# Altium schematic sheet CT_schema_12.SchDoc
size 390 x 278 mm
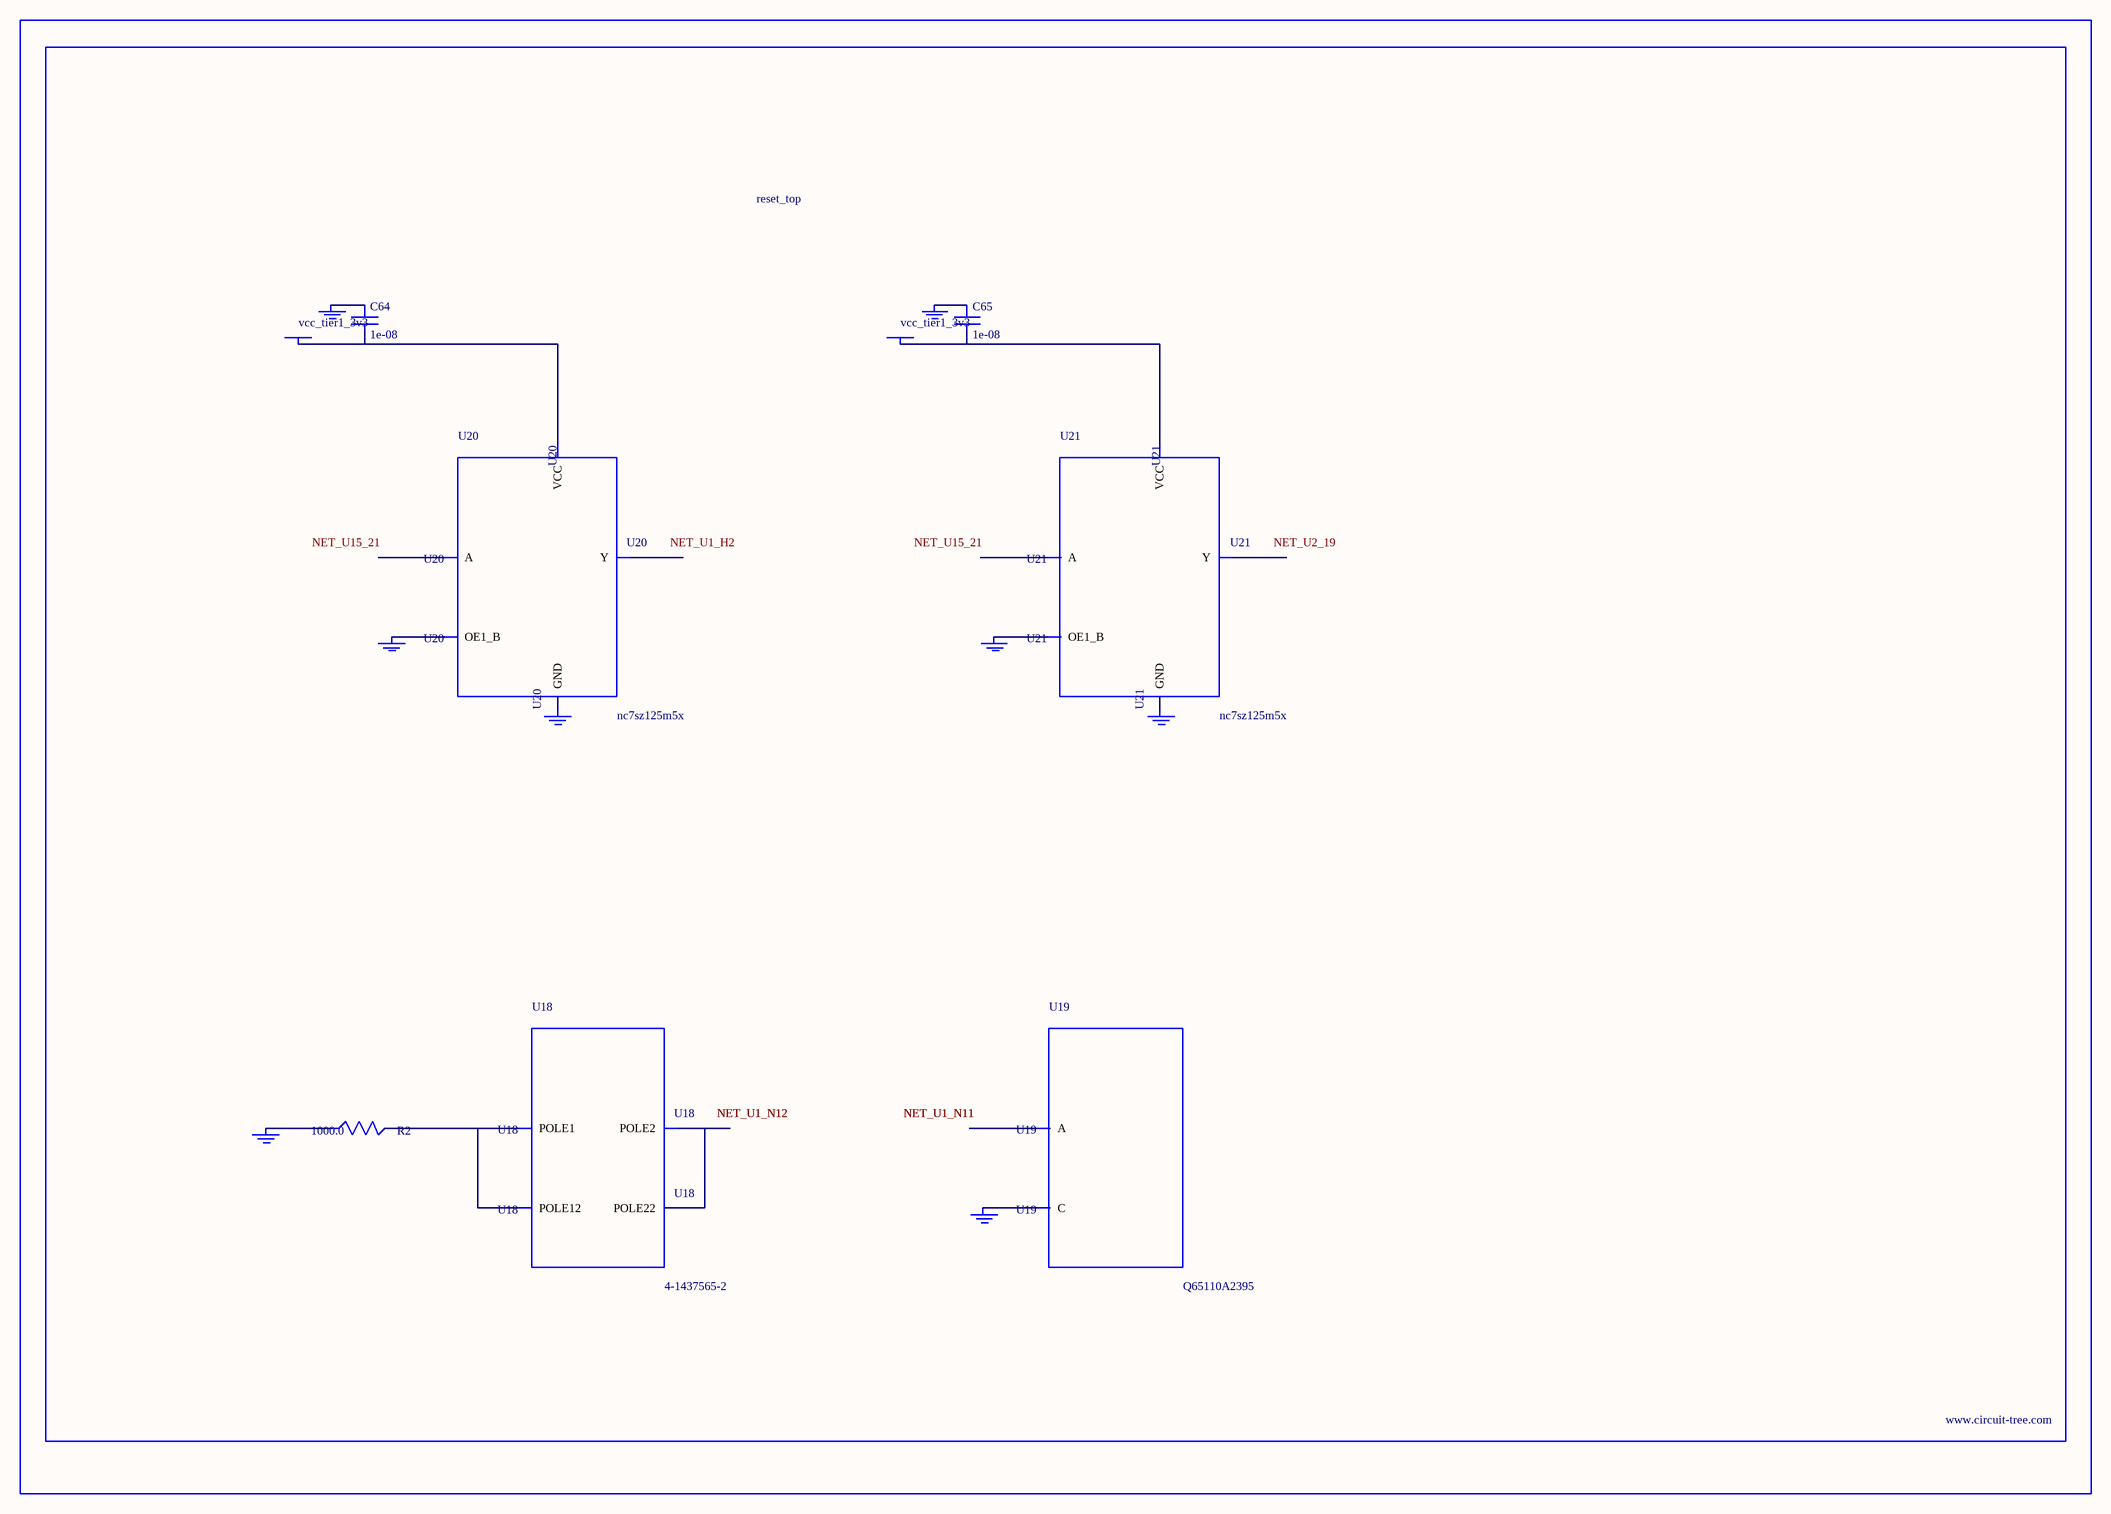
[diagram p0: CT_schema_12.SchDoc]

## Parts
BORDER11  (no value)
C64  1e-08  [C0402]
C65  1e-08  [C0402]
GND_INSTANCE_11_0  (no value)
GND_INSTANCE_11_1  (no value)
GND_INSTANCE_11_2  (no value)
GND_INSTANCE_11_3  (no value)
GND_INSTANCE_11_4  (no value)
GND_INSTANCE_11_5  (no value)
GND_INSTANCE_11_6  (no value)
GND_INSTANCE_11_7  (no value)
POWER_INSTANCE_11_0  vcc_tier1_3v3
POWER_INSTANCE_11_1  vcc_tier1_3v3
R2  1000.0  [R0603]
U18  4-1437565-2  [SW_4-1437565-2]
U19  Q65110A2395  [LGM67K-G1J2-24-Z]
U20  nc7sz125m5x  [NC7SZ125M5X]
U21  nc7sz125m5x  [NC7SZ125M5X]

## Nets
NetC64_1: C64.1 GND_INSTANCE_11_2.0(GND)
NetC64_2: C64.2 POWER_INSTANCE_11_0.0(PWR) U20.5(VCC)
NetC65_1: C65.1 GND_INSTANCE_11_5.0(GND)
NetC65_2: C65.2 POWER_INSTANCE_11_1.0(PWR) U21.5(VCC)
NetGND_INSTANCE_11_0_0: GND_INSTANCE_11_0.0(GND) R2.1
NetGND_INSTANCE_11_1_0: GND_INSTANCE_11_1.0(GND) U19.C
NetGND_INSTANCE_11_3_0: GND_INSTANCE_11_3.0(GND) U20.1(OE1_B)
NetGND_INSTANCE_11_4_0: GND_INSTANCE_11_4.0(GND) U20.3(GND)
NetGND_INSTANCE_11_6_0: GND_INSTANCE_11_6.0(GND) U21.1(OE1_B)
NetGND_INSTANCE_11_7_0: GND_INSTANCE_11_7.0(GND) U21.3(GND)
NetR2_2: R2.2 U18.1(POLE1) U18.2(POLE12)
NetU18_3: U18.3(POLE2) U18.4(POLE22)

Not connected (* = marked no-connect by the designer): U19 A; U20 2(A) 4(Y); U21 2(A) 4(Y)

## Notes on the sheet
- Labels drawn without touching a wire or pin: NET_U1_H2, NET_U2_19, NET_U15_21

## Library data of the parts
BORDER11 = BORDER_PAGE11
C64 C65 = C0402C103K3RAC
GND_INSTANCE_11_0-GND_INSTANCE_11_7 = GND
POWER_INSTANCE_11_0 POWER_INSTANCE_11_1 = PWR
R2 = RC0603JR-071KL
